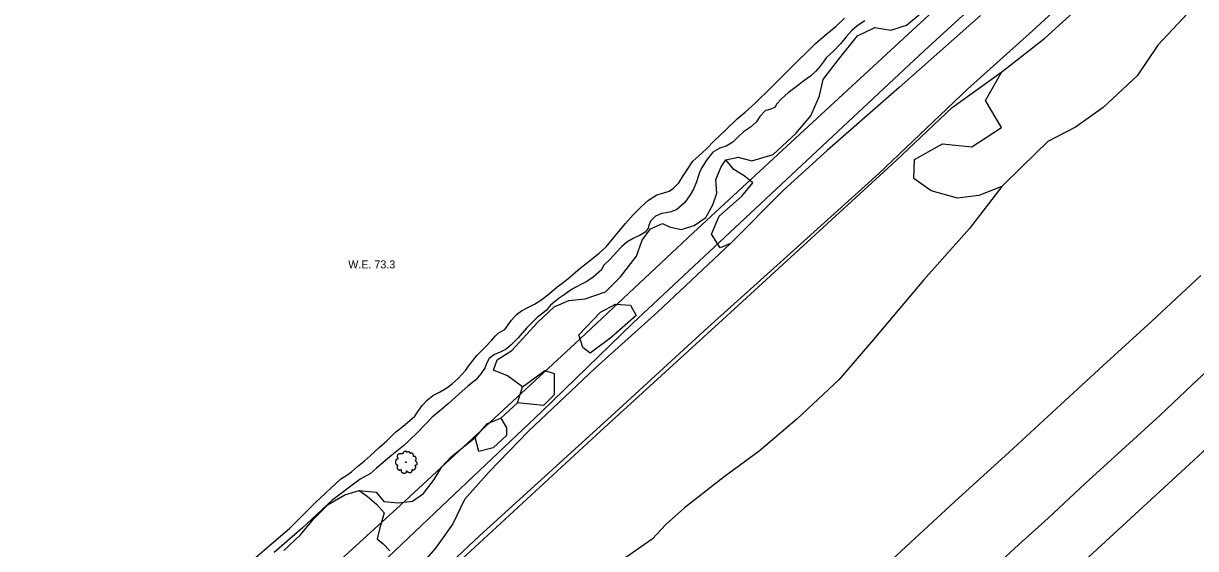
# Model space of a CAD drawing. Extents: x 2161152 to 2175754, y 602179 to 617749.
# Drawn here: x 2170580 to 2171166, y 612709 to 612971 of the extents above; entities that cross this region are included whole.
import ezdxf

# ---------------------------------------------------------------- set-up
doc = ezdxf.new("R2010")
doc.units = 0
for name, color, linetype in [('RD_EX_DR_ErosCtrl', 7, 'Continuous'), ('RD_EX_Fence_Other', 7, 'Continuous'), ('RD_EX_GuardRail', 7, 'Continuous'), ('RD_EX_H2O', 7, 'Continuous'), ('RD_EX_H2O_txCode', 7, 'Continuous'), ('RD_EX_Road', 7, 'Continuous'), ('RD_EX_VEG', 7, 'Continuous')]:
    doc.layers.add(name, color=color, linetype=linetype)

msp = doc.modelspace()

# ---------------------------------------------------------------- linework, layer by layer
at = {"layer": 'RD_EX_DR_ErosCtrl'}
msp.add_lwpolyline([(2171000.74, 612972.7), (2170996.94, 612970.19), (2170994.31, 612967.87), (2170991.48, 612964.59), (2170988.65, 612961.25), (2170985.27, 612957.6), (2170981.47, 612954.12), (2170979.97, 612952.02), (2170978.51, 612949.95), (2170976.24, 612947.45), (2170973.7, 612945.03), (2170970.31, 612942.63), (2170966.53, 612939.69), (2170962.54, 612936.68), (2170959.19, 612933.76), (2170956.65, 612931.06), (2170956.03, 612929.46), (2170953.84, 612928.45), (2170952.23, 612927.97), (2170951.07, 612927.92), (2170948.28, 612924.94), (2170946.42, 612921.99), (2170943.59, 612919.6), (2170940.09, 612917.18), (2170937.63, 612914.95), (2170934.84, 612911.97), (2170931.46, 612910.03), (2170928.41, 612908.98), (2170924.89, 612906.99), (2170921.6, 612902.97), (2170919.56, 612899.53), (2170918.39, 612897.35), (2170917.62, 612895.36), (2170916.65, 612892.28), (2170915.16, 612888.53), (2170913.57, 612885.64), (2170910.82, 612881.86), (2170906.89, 612878.39), (2170904, 612877.17), (2170901.47, 612876.8), (2170899.2, 612876.35), (2170896.14, 612875.1), (2170893.67, 612872.6), (2170892.9, 612870.41), (2170892.48, 612869.07), (2170891.06, 612867.1), (2170888.55, 612865.6), (2170884.95, 612863.84), (2170881.84, 612862.1), (2170879.14, 612859.78), (2170876.83, 612857.18), (2170873.52, 612853.65), (2170870.23, 612850.46), (2170869.19, 612848.21), (2170865.12, 612844.61), (2170861.83, 612842.38), (2170858.83, 612840.93), (2170854.24, 612838.44), (2170850.47, 612835.76), (2170848.1, 612834.06), (2170843.8, 612830.51), (2170841.59, 612828), (2170837.06, 612824.49), (2170831.71, 612819.12), (2170827.63, 612814.3), (2170823.93, 612810.66), (2170821.54, 612808.63), (2170818.51, 612807.15), (2170815.79, 612805.89), (2170813.13, 612803.86), (2170811.72, 612801.47), (2170811.02, 612799.41), (2170808.89, 612796.27), (2170806.33, 612793.25), (2170802.45, 612790.08), (2170799.58, 612787.67), (2170796.05, 612784.38), (2170792.67, 612781.49), (2170789.28, 612778.4), (2170784.61, 612774.56), (2170781.21, 612771.07), (2170776.95, 612766.65), (2170770.2, 612760.37), (2170764.51, 612755.7), (2170756.82, 612749.12), (2170753.78, 612746.55), (2170748.65, 612743.69), (2170734.44, 612732.91), (2170719.68, 612719.11), (2170705.64, 612707.01)], dxfattribs=at)
at = {"layer": 'RD_EX_Fence_Other'}
msp.add_lwpolyline([(2171629.93, 613183.69), (2171565.47, 613123.14), (2171460.73, 613025.9), (2171380.41, 612952.09), (2171311.67, 612888.45), (2171230.21, 612813.09), (2171160.82, 612749.11), (2171079.12, 612673.79), (2171009.01, 612608.99), (2170939.02, 612544.07), (2170892.68, 612501.31), (2170846.44, 612458.66), (2170811.55, 612426.42), (2170753.62, 612372.89), (2170696.66, 612320.47), (2170651, 612278.15), (2170593.59, 612225.56), (2170547.2, 612182.57), (2170488.47, 612128.36), (2170441.67, 612084.8), (2170394.27, 612040.81), (2170334.36, 611985.65), (2170252.46, 611910.1)], dxfattribs=at)
at = {"layer": 'RD_EX_GuardRail'}
msp.add_lwpolyline([(2171387.66, 613284.24), (2171360.53, 613261), (2171316.04, 613226.68), (2171233.01, 613158.75), (2171192.11, 613121.93), (2171130.74, 613065.53), (2171026.54, 612969.89), (2170964.01, 612912.04), (2170914.96, 612866.74), (2170856.02, 612811.47), (2170768.69, 612730.64), (2170647.39, 612620.03), (2170571.8, 612549.61), (2170465.23, 612450.49), (2170410.37, 612399.58), (2170364.82, 612357.5), (2170313.9, 612311.8), (2170284.58, 612283.5), (2170219.87, 612223.54)], dxfattribs=at)
at = {"layer": 'RD_EX_H2O'}
msp.add_lwpolyline([(2170690.35, 612699.38), (2170704.26, 612711.36), (2170713.26, 612719.01), (2170726.14, 612731.81), (2170738.99, 612743.83), (2170741.49, 612745.33), (2170744.31, 612747.25), (2170747.22, 612749.9), (2170750.53, 612752.66), (2170753.6, 612755.33), (2170758.09, 612759.51), (2170761.92, 612762.88), (2170766.51, 612767.22), (2170769.88, 612769.92), (2170775.97, 612775.2), (2170777.57, 612777.59), (2170779.56, 612780.4), (2170782.07, 612783.06), (2170784.91, 612785.38), (2170788.22, 612787.18), (2170791.84, 612789.34), (2170794.73, 612791.52), (2170797.53, 612794), (2170801.22, 612798.01), (2170803.31, 612800.85), (2170806.94, 612805.39), (2170810.72, 612809.23), (2170814.37, 612813.14), (2170816.31, 612815.33), (2170817.61, 612816.54), (2170819.1, 612817.48), (2170820.96, 612818.51), (2170822.49, 612820.77), (2170824.17, 612823.09), (2170826.72, 612825.85), (2170829.17, 612827.75), (2170832.31, 612829.4), (2170835.68, 612831.06), (2170839.41, 612833.45), (2170843.16, 612836.5), (2170847.12, 612839.8), (2170849.39, 612841.47), (2170852.36, 612843.72), (2170858.57, 612849), (2170861.33, 612851.18), (2170864.95, 612854.1), (2170868.02, 612856.64), (2170871.47, 612859.73), (2170874.72, 612863.59), (2170877.67, 612867.16), (2170881.26, 612871.41), (2170885.09, 612875.74), (2170889.22, 612879.9), (2170892.74, 612883.06), (2170896.91, 612885.79), (2170900.29, 612886.76), (2170902.97, 612887.59), (2170905.17, 612889.01), (2170907.82, 612891.79), (2170909.65, 612894.71), (2170911.96, 612898.27), (2170914.9, 612902.54), (2170917.73, 612904.99), (2170921.74, 612908.72), (2170925.52, 612912.63), (2170931.25, 612918.16), (2170937.02, 612923.78), (2170940.91, 612926.96), (2170945.87, 612931.32), (2170954, 612939.28), (2170957.37, 612942.67), (2170961.87, 612947.11), (2170967.33, 612952.72), (2170971.96, 612957.16), (2170976.18, 612961.28), (2170980.97, 612965.48), (2170986.26, 612969.9), (2170990.62, 612974.02)], dxfattribs=at)
at = {"layer": 'RD_EX_Road'}
for points in [[(2171390.26, 613283.49), (2171386.95, 613281.97), (2171333.44, 613235.7), (2171298.61, 613205.8), (2171238.47, 613151.31), (2171183.23, 613099.37), (2171131.27, 613050.72), (2171067.13, 612991.37), (2171030.54, 612957.86), (2170987.28, 612917.32), (2170930.69, 612864.41), (2170884.83, 612821.54), (2170839.21, 612777.22), (2170795.73, 612736.07), (2170752.88, 612695.49), (2170669.97, 612621.67), (2170613.47, 612571.64), (2170547.87, 612512.59), (2170504.72, 612472.8), (2170477.35, 612447.97), (2170413.48, 612389.58), (2170349.48, 612331.58), (2170272.08, 612260.29)], [(2170263.08, 612211.32), (2170307.81, 612252.14), (2170341.19, 612282.26), (2170375.38, 612313.39), (2170424.08, 612358.1), (2170450.38, 612382.16), (2170475.88, 612405.73), (2170526.35, 612453.13), (2170583.53, 612506.21), (2170620, 612539.16), (2170653.7, 612570.04), (2170697.97, 612611.68), (2170774.42, 612683.54), (2170808.25, 612715.29), (2170842.85, 612746.88), (2170877.87, 612778.6), (2170922.27, 612819.35), (2170963.45, 612856.33), (2171007.77, 612896.36), (2171052.15, 612938.49), (2171084.52, 612967.75), (2171110.71, 612991.76)], [(2171007.45, 612696.93), (2171028.19, 612716.38), (2171047.58, 612734.13), (2171072.77, 612756.98), (2171098.69, 612780.9), (2171119.76, 612800.34), (2171144.13, 612822.65), (2171168.61, 612845.39)], [(2171185.46, 612810.49), (2171164.28, 612790.76), (2171148.4, 612775.71), (2171132.95, 612761.71), (2171110.93, 612741.45), (2171092.41, 612724.2), (2171077.72, 612710.96), (2171060.12, 612694.7)]]:
    msp.add_lwpolyline(points, dxfattribs=at)
at = {"layer": 'RD_EX_VEG'}
msp.add_line((2170818.85, 612774.06), (2170827.15, 612781.79), dxfattribs=at)
for points in [[(2171161.98, 612976.34), (2171147.12, 612960.46), (2171136.79, 612945.22), (2171119.82, 612929.41), (2171105.98, 612919.59), (2171092.23, 612912.4), (2171079.35, 612899.9), (2171069.21, 612889.94), (2171057.67, 612885.33), (2171047.05, 612884.12), (2171033.97, 612887.75), (2171025.22, 612893.87), (2171025.56, 612903.33), (2171039.53, 612911.26), (2171054.23, 612909.69), (2171069.1, 612919.45), (2171061.14, 612932.92), (2171069.28, 612947.11), (2171090.68, 612963.99), (2171115.45, 612986.54)], [(2171058.53, 612975.37), (2171017.9, 612939.31), (2170981.9, 612907.82), (2170960.14, 612888.07), (2170933.67, 612861.37), (2170928.46, 612859.32), (2170924.23, 612866.05), (2170927.97, 612875.14), (2170939.38, 612885), (2170944.76, 612891.79), (2170940.53, 612895.23), (2170935.37, 612898.31), (2170931.32, 612903.21), (2170937.45, 612904.58), (2170944.27, 612902.75), (2170954.95, 612905.81), (2170966.29, 612916.37), (2170973.88, 612925.22), (2170978.06, 612935.24), (2170979.94, 612943.36), (2170987.7, 612953.4), (2170997.12, 612965.24), (2171005.86, 612969.29), (2171013.74, 612967.95), (2171021.61, 612970.45), (2171031.27, 612978.42)], [(2170297.61, 612239.81), (2170396.2, 612328.43), (2170457.98, 612384.15), (2170527.22, 612450.41), (2170602.1, 612519.92), (2170706.63, 612617.13), (2170788.66, 612693.64), (2170868.65, 612767.63), (2170933.53, 612826.78), (2171016.39, 612902.93), (2171044.44, 612929.31), (2171069.28, 612947.11)], [(2170829.67, 612789.73), (2170822.22, 612795.26), (2170815.2, 612798.15), (2170817.1, 612803.24), (2170824.41, 612808.01), (2170837.35, 612822.08), (2170845.57, 612829.73), (2170852.83, 612832.92), (2170861.06, 612833.68), (2170871.25, 612837.29), (2170878.67, 612844.71), (2170886.71, 612855.01), (2170889.51, 612862.99), (2170893.69, 612868.67), (2170899.61, 612871.37), (2170903.25, 612869.66), (2170909.02, 612868.39), (2170915.57, 612870.41), (2170921.26, 612874.43), (2170924.78, 612880.77), (2170926.84, 612886.51), (2170926.29, 612893.39), (2170929.02, 612899.77), (2170931.32, 612903.21)], [(2171069.21, 612889.94), (2171053.11, 612868.82), (2171030.1, 612843.05), (2171005.1, 612813.37), (2170987.85, 612793.22), (2170966.91, 612773.72), (2170947.95, 612757.6), (2170930.44, 612744.86), (2170910.7, 612729.29), (2170901.28, 612721.03), (2170894.54, 612713.73), (2170879.75, 612703.28), (2170863.36, 612695.93), (2170841.1, 612680.06), (2170830.65, 612668.53), (2170824, 612660.04), (2170810.72, 612646.69)], [(2170933.67, 612861.37), (2170897.32, 612827.27), (2170866.05, 612799.17), (2170832.69, 612767.59), (2170813.02, 612747.24), (2170800.69, 612733.47), (2170795, 612721.3), (2170786.27, 612709.12), (2170780.65, 612702.61), (2170774.17, 612698.1), (2170771.88, 612696.47), (2170762.71, 612689.68), (2170753.32, 612684.21), (2170741.23, 612676.72), (2170729.65, 612668.69), (2170717.47, 612658.58), (2170703.09, 612645.39), (2170684.1, 612628.14), (2170668.57, 612612.1), (2170654.72, 612599.15), (2170625.33, 612569.9), (2170606.6, 612552.38), (2170587.36, 612535.41), (2170573.81, 612523.25)], [(2170886.6, 612825.47), (2170873.97, 612814.47), (2170863.56, 612806.55), (2170859.84, 612809.44), (2170857.83, 612815.7), (2170868.63, 612827.03), (2170876.27, 612831.1), (2170883.63, 612830.57), (2170886.6, 612825.47)], [(2170845.58, 612785.74), (2170840.26, 612780.53), (2170827.15, 612781.79), (2170829.67, 612789.73), (2170840.88, 612797.88), (2170845.56, 612796.4), (2170845.58, 612785.74)], [(2170821.7, 612765.54), (2170815.03, 612759.32), (2170807.86, 612757.47), (2170806.14, 612764.51), (2170812.31, 612771.53), (2170818.85, 612774.06), (2170821.71, 612769.35), (2170821.7, 612765.54)], [(2170748.07, 612738.05), (2170756.58, 612737.11), (2170760.38, 612732.48), (2170767.61, 612731.83), (2170774.76, 612732.63), (2170780.3, 612736.52), (2170785.56, 612743.45), (2170789.34, 612749.78), (2170794.14, 612754.75), (2170806.14, 612764.51)], [(2170710.39, 612707.95), (2170718.87, 612715.87), (2170725.22, 612723.6), (2170732.61, 612731.03), (2170740.98, 612735.78), (2170748.07, 612738.05), (2170752.07, 612735.14), (2170756.82, 612731.16), (2170760.62, 612726.82), (2170758.52, 612719.26), (2170757.16, 612713.91), (2170760.1, 612711.31), (2170763.4, 612707.78)]]:
    msp.add_lwpolyline(points, dxfattribs=at)
for centre, radius in [((2170771.4, 612752.18), 0.188), ((2170771.39, 612752.17), 0.000075)]:
    msp.add_circle(centre, radius, dxfattribs=at)
for points in [[(2170771.5, 612757.56), (2170771.27, 612757.58), (2170771.03, 612757.5), (2170770.84, 612757.43), (2170770.67, 612757.37), (2170770.5, 612757.29), (2170770.28, 612757.16), (2170770.11, 612757.01), (2170770.02, 612756.83), (2170769.98, 612756.66), (2170769.94, 612756.45), (2170769.94, 612756.32), (2170769.85, 612756.3), (2170769.73, 612756.32), (2170769.55, 612756.38), (2170769.36, 612756.38), (2170769.17, 612756.38), (2170768.91, 612756.36), (2170768.65, 612756.36), (2170768.44, 612756.32), (2170768.2, 612756.28), (2170767.92, 612756.19), (2170767.65, 612756.09), (2170767.43, 612755.91), (2170767.24, 612755.55), (2170767.15, 612755.29), (2170767.04, 612755.1), (2170767.15, 612754.76), (2170767.28, 612754.5), (2170767.3, 612754.35), (2170767.35, 612754.03), (2170767.43, 612753.86), (2170767.52, 612753.71), (2170767.47, 612753.7), (2170767.19, 612753.66), (2170766.96, 612753.58), (2170766.64, 612753.41), (2170766.47, 612753.25), (2170766.4, 612753), (2170766.38, 612752.74), (2170766.3, 612752.59), (2170766.25, 612752.38), (2170766.23, 612752.33), (2170766.19, 612752.08), (2170766.27, 612751.75), (2170766.29, 612751.48), (2170766.38, 612751.32), (2170766.49, 612751.18), (2170766.62, 612751), (2170766.92, 612750.83), (2170767.17, 612750.75), (2170767.32, 612750.73), (2170767.19, 612750.36), (2170767.15, 612750.1), (2170767.05, 612749.8), (2170767.05, 612749.74), (2170767.02, 612749.39), (2170767.13, 612749.14), (2170767.19, 612748.86), (2170767.32, 612748.69), (2170767.52, 612748.47), (2170767.77, 612748.3), (2170768.14, 612748.2), (2170768.44, 612748.22), (2170768.87, 612748.35), (2170769.06, 612748.41), (2170769.04, 612748.28), (2170769.06, 612748), (2170769.06, 612747.68), (2170769.17, 612747.44), (2170769.25, 612747.23), (2170769.36, 612747.04), (2170769.6, 612746.87), (2170769.9, 612746.82), (2170770.22, 612746.71), (2170770.56, 612746.65), (2170770.93, 612746.63), (2170771.38, 612746.74), (2170771.59, 612746.84), (2170771.66, 612746.97), (2170771.81, 612747.25), (2170771.78, 612747.42), (2170771.8, 612747.87), (2170771.87, 612747.74), (2170772, 612747.47), (2170772.38, 612747.25), (2170772.68, 612747.12), (2170773.03, 612747.01), (2170773.26, 612746.95), (2170773.61, 612747.01), (2170773.9, 612747.06), (2170774.18, 612747.16), (2170774.4, 612747.36), (2170774.53, 612747.57), (2170774.57, 612747.77), (2170774.63, 612748.05), (2170774.66, 612748.19)], [(2170774.66, 612748.19), (2170774.61, 612748.32), (2170774.57, 612748.5), (2170774.63, 612748.49), (2170774.76, 612748.45), (2170774.96, 612748.35), (2170775.13, 612748.3), (2170775.38, 612748.32), (2170775.58, 612748.39), (2170775.92, 612748.6), (2170776.13, 612748.95), (2170776.33, 612749.25), (2170776.39, 612749.5), (2170776.35, 612749.67), (2170776.33, 612750.04), (2170776.18, 612750.23), (2170776.14, 612750.32), (2170776.07, 612750.62), (2170776.13, 612750.66), (2170776.33, 612750.7), (2170776.61, 612750.79), (2170776.82, 612750.88), (2170776.99, 612751.02), (2170777.04, 612751.18), (2170777.03, 612751.48), (2170777.06, 612751.78), (2170777.01, 612751.9), (2170776.93, 612752.01), (2170776.88, 612752.16), (2170776.76, 612752.27), (2170776.69, 612752.38), (2170776.61, 612752.46), (2170776.52, 612752.57), (2170776.39, 612752.67), (2170776.28, 612752.7), (2170776.24, 612752.82), (2170776.35, 612752.97), (2170776.39, 612753.04), (2170776.41, 612753.21), (2170776.58, 612753.47), (2170776.61, 612753.77), (2170776.58, 612754.09), (2170776.54, 612754.3), (2170776.43, 612754.5), (2170776.28, 612754.69), (2170776.18, 612754.82), (2170776.05, 612754.91), (2170775.81, 612755.01), (2170775.62, 612755.05), (2170775.36, 612755.05), (2170775.21, 612755.08), (2170775.23, 612755.12), (2170775.23, 612755.23), (2170775.23, 612755.44), (2170775.17, 612755.78), (2170775.06, 612756.15), (2170775.06, 612756.17), (2170774.98, 612756.36), (2170774.81, 612756.51), (2170774.68, 612756.58), (2170774.53, 612756.68), (2170774.34, 612756.69), (2170774.12, 612756.69), (2170773.91, 612756.66), (2170773.76, 612756.58), (2170773.63, 612756.49), (2170773.58, 612756.6), (2170773.5, 612756.83), (2170773.46, 612756.94), (2170773.35, 612757.07), (2170773.18, 612757.22), (2170772.85, 612757.31), (2170772.38, 612757.26), (2170772.15, 612757.11), (2170772.04, 612756.98), (2170772, 612757.07), (2170771.85, 612757.22), (2170771.78, 612757.35), (2170771.65, 612757.44), (2170771.53, 612757.52), (2170771.46, 612757.56)]]:
    msp.add_spline(points, degree=3, dxfattribs=at)

# ---------------------------------------------------------------- texts
at = {"layer": 'RD_EX_H2O_txCode'}
msp.add_text('W.E. 73.3', height=4, dxfattribs=at).set_placement((2170742.66, 612848.96))

doc.saveas('drawing.dxf')
